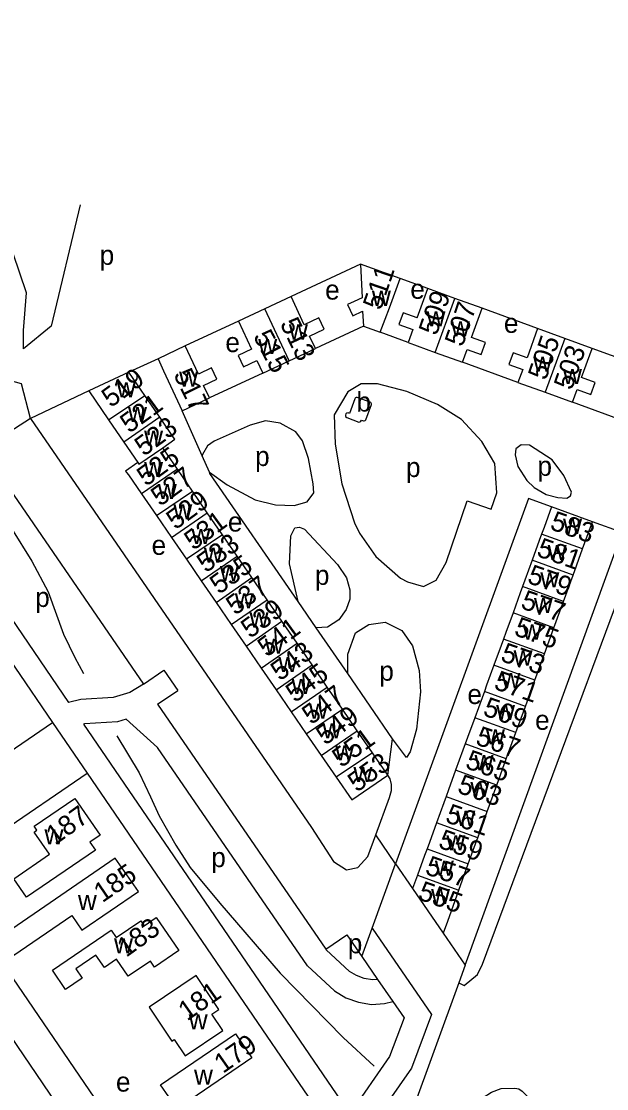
# Model space of a CAD drawing. Extents: x 154320 to 156262, y 382651 to 384180.
# Drawn here: x 155711.8 to 155831.3, y 383414.4 to 383632.2 of the extents above; entities that cross this region are included whole.
import ezdxf

# ---------------------------------------------------------------- set-up
doc = ezdxf.new("R2010")
doc.units = 0
for name, color, linetype in [('BLT_Basislijn', 7, 'Continuous'), ('BLT_Bebouwing', 7, 'Continuous'), ('BLT_Centroide', 7, 'Continuous'), ('BLT_Huisnummer', 7, 'Continuous'), ('BLT_Huisnummer_ tussenligend', 7, 'Continuous'), ('BLT_Onderverdeling_panden', 7, 'Continuous'), ('BLT_Vlakafsluiter', 7, 'Continuous')]:
    doc.layers.add(name, color=color, linetype=linetype)

msp = doc.modelspace()

# ---------------------------------------------------------------- linework, layer by layer
at = {"layer": 'BLT_Basislijn'}
for p, q in [((155723.77, 383594.72), (155717.9, 383569.98)), ((155781.07, 383582.65), (155766.86, 383576.05)), ((155794.76, 383577.69), (155789.13, 383579.71)), ((155817.21, 383569.54), (155805.91, 383573.63)), ((155717.9, 383569.98), (155712.22, 383565.38)), ((155756.13, 383571.03), (155745.24, 383565.96)), ((155781.64, 383569.99), (155771.84, 383565.42)), ((155790.76, 383566.65), (155785.09, 383568.73)), ((155839.44, 383561.42), (155828.37, 383565.46)), ((155739.71, 383563.35), (155733.71, 383560.61)), ((155813.2, 383558.51), (155801.9, 383562.62)), ((155761.08, 383560.4), (155750.18, 383555.34)), ((155835.65, 383550.35), (155824.35, 383554.45)), ((155748.71, 383543.49), (155744.6, 383552.72)), ((155750.19, 383540.18), (155748.71, 383543.49)), ((155778.43, 383499.07), (155772, 383508.41)), ((155736.76, 383496.93), (155740.88, 383499.77)), ((155740.88, 383499.77), (155743.72, 383495.64)), ((155787.59, 383485.76), (155778.43, 383499.07)), ((155739.6, 383492.81), (155743.72, 383495.64)), ((155739.6, 383492.81), (155773.99, 383442.8)), ((155689.88, 383469.84), (155718.17, 383489.1)), ((155695.34, 383458.35), (155725.22, 383478.78)), ((155788.18, 383460.25), (155791.67, 383455.18)), ((155695.34, 383458.35), (155746.12, 383384.05)), ((155736.8, 383385.3), (155689.56, 383454.4)), ((155781.31, 383441.34), (155784.53, 383436.66)), ((155802.41, 383439.57), (155801.1, 383435.95)), ((155784.53, 383436.66), (155787.63, 383432.15)), ((155801.1, 383435.95), (155788.64, 383401.73))]:
    msp.add_line(p, q, dxfattribs=at)
for points in [[(155712.22, 383565.38), (155712.25, 383569.11), (155712.86, 383576.76), (155710.15, 383584.83), (155703.72, 383589.45), (155702.06, 383598.56), (155698.39, 383604.03), (155691.52, 383607.97), (155684.3, 383610.54), (155677.08, 383613.11), (155657.33, 383632.2)], [(155713.63, 383551.16), (155711.84, 383558.19), (155704.16, 383560.3), (155698.52, 383562.36), (155692.32, 383562.27)], [(155725.56, 383556.77), (155713.63, 383551.16)], [(155699.18, 383552.32), (155699.56, 383547.02), (155700.26, 383542.84), (155701.35, 383540.44), (155704.4, 383535.59), (155709.75, 383528.69), (155713.91, 383522), (155717.27, 383515.75), (155720.43, 383507.15), (155722.7, 383502.36), (155724.5, 383499.1)], [(155713.63, 383551.16), (155703.82, 383544.84), (155736.76, 383496.93)], [(155713.63, 383551.16), (155771.03, 383467.65), (155775.5, 383460.75), (155778.15, 383458.99), (155780.51, 383459.46), (155782.53, 383461.72), (155784.15, 383466.14)], [(155750.19, 383540.18), (155753.83, 383537.57), (155759.51, 383534.55), (155763.68, 383533.5), (155767.47, 383533.36), (155770.12, 383534.12), (155771.53, 383535.96), (155771.41, 383537.8), (155770.4, 383542.99), (155769.19, 383546.57), (155767.83, 383548.45), (155764.67, 383550.18), (155761.67, 383550.66), (155758.53, 383549.75)], [(155758.53, 383549.75), (155751.17, 383546.54), (155749.78, 383545.57), (155748.77, 383543.82), (155748.71, 383543.49)], [(155768.3, 383513.79), (155750.3, 383539.93), (155750.19, 383540.18)], [(155815.36, 383534.83), (155788.18, 383460.25)], [(155820.06, 383533.12), (155815.36, 383534.83)], [(155651.71, 383522.17), (155669.01, 383530.29), (155671.62, 383531.32), (155674.82, 383532.09), (155679.01, 383532.3), (155683.15, 383531.66), (155687.05, 383530.13), (155690.62, 383527.92), (155693.07, 383525.51), (155695.02, 383522.96), (155718.17, 383489.1)], [(155768.3, 383513.79), (155766.56, 383521.48), (155766.84, 383527.19), (155767.66, 383528.8), (155768.61, 383528.97), (155769.58, 383528.54), (155776.35, 383521.32), (155778.18, 383518.65), (155778.89, 383516.2), (155778.87, 383514.26), (155778.11, 383512.13), (155776.63, 383510.07), (155774.32, 383508.58), (155772, 383508.41)], [(155834.5, 383527.86), (155828.41, 383530.07)], [(155802.41, 383439.57), (155834.5, 383527.86)], [(155699.07, 383525.89), (155721.42, 383493.2)], [(155801.1, 383435.95), (155802.24, 383435.39), (155804.95, 383437.68), (155805.97, 383439.73), (155834.64, 383517.07), (155835.62, 383518.64), (155836.89, 383519.06), (155839.22, 383519.08), (155863.38, 383510.83), (155865.12, 383510.28), (155870.15, 383508.84), (155869.25, 383505.27), (155870.15, 383504.05), (155871.64, 383502.96)], [(155772, 383508.41), (155768.3, 383513.79)], [(155778.43, 383499.07), (155778.43, 383503.05), (155780.02, 383507.41), (155782.72, 383509.07), (155786.1, 383509.56), (155789.48, 383507.89), (155789.48, 383507.89), (155791.67, 383504.76), (155793.03, 383499.67), (155793.28, 383495.37), (155792.48, 383487.74), (155791.19, 383483.13), (155790.42, 383481.94), (155787.59, 383485.76)], [(155736.76, 383496.93), (155733.93, 383495.18), (155730.57, 383494.2), (155723.96, 383493.77), (155721.42, 383493.2)], [(155718.17, 383489.1), (155725.22, 383478.78)], [(155733.18, 383489.76), (155731.44, 383489.25), (155724.67, 383488.8), (155724.46, 383488.76)], [(155770.25, 383439.41), (155739.62, 383483.96), (155733.18, 383489.76)], [(155724.46, 383488.76), (155778.83, 383409.21)], [(155731.27, 383486.4), (155735.86, 383478.8), (155738.14, 383473.92), (155739.95, 383470.03), (155743.32, 383464.03), (155746.24, 383459.5), (155752.33, 383452.24), (155764.66, 383437.95), (155777.51, 383424.78), (155783.83, 383418.94)], [(155786.63, 383478.34), (155787.59, 383485.76)], [(155725.22, 383478.78), (155776.01, 383404.48)], [(155784.15, 383466.14), (155786.93, 383473.75), (155787.37, 383475.22), (155787.37, 383476.43), (155787.09, 383477.6), (155786.63, 383478.34)], [(155783.41, 383447.12), (155788.18, 383460.25)], [(155773.99, 383442.8), (155778.25, 383445.76), (155781.31, 383441.34)], [(155781.31, 383441.34), (155783.41, 383447.12)], [(155783.41, 383447.12), (155795.54, 383429.47), (155791.45, 383418.56), (155781.85, 383404.79)], [(155797.95, 383446.06), (155802.41, 383439.57)], [(155784.53, 383436.66), (155783.49, 383436.59), (155781.82, 383436.86), (155780.2, 383437.42), (155778.81, 383438.28), (155774.06, 383442.7), (155773.99, 383442.8)], [(155770.25, 383439.41), (155775.76, 383434.29), (155778.05, 383432.87), (155780.6, 383432), (155783.26, 383431.56), (155785.95, 383431.75), (155787.63, 383432.15)], [(155787.63, 383432.15), (155789.95, 383428.78), (155786.99, 383420.9), (155778.83, 383409.21)]]:
    msp.add_lwpolyline(points, dxfattribs=at)
for points in [[(155784.52, 383558.23), (155781.17, 383558.23), (155778.45, 383556.56), (155775.64, 383551.88), (155775.88, 383545.9), (155777.21, 383537.81), (155779.85, 383529.83), (155780.81, 383527.76), (155784.17, 383522.98), (155789.18, 383518.56), (155790.64, 383517.77), (155793.88, 383516.88), (155796.51, 383518.11), (155798.54, 383521.73), (155802.8, 383534.35), (155807.69, 383532.62), (155808.86, 383535.94), (155808.49, 383541.93), (155805.84, 383546.45), (155801.65, 383550.96), (155796.77, 383553.98), (155790.52, 383556.64)], [(155823.18, 383534.9), (155823.92, 383535.32), (155824.1, 383536.13), (155822.59, 383539.53), (155820.21, 383542.67), (155815.58, 383545.72), (155813.83, 383545.77), (155812.78, 383544.93), (155812.61, 383543.72), (155813.2, 383541.35), (155815.02, 383538.47), (155816.49, 383537.05), (155818.92, 383535.6), (155821.3, 383535.03)], [(155804.58, 383408.39), (155804.7, 383409.7), (155805.12, 383411.15), (155806.09, 383412.58), (155807.78, 383413.64), (155809.74, 383414.38), (155812.53, 383414.47), (155813.38, 383414.34), (155814.07, 383413.82), (155816.13, 383411.78), (155817.37, 383409.78), (155818.05, 383407.74), (155818.02, 383406.53), (155816.72, 383403.75), (155815.78, 383403), (155814.4, 383402.09), (155813.12, 383401.41), (155811.21, 383400.86), (155810.01, 383400.98), (155809.47, 383401.2), (155806.52, 383403.11), (155805.89, 383403.67), (155805.69, 383403.98), (155804.92, 383406.4)]]:
    msp.add_lwpolyline(points, close=True, dxfattribs=at)
at = {"layer": 'BLT_Bebouwing'}
for p, q in [((155781.07, 383582.65), (155781.36, 383575.79)), ((155789.13, 383579.71), (155781.07, 383582.65)), ((155786.94, 383573.75), (155789.13, 383579.71)), ((155792.6, 383571.71), (155794.76, 383577.69)), ((155800.33, 383575.66), (155794.76, 383577.69)), ((155766.86, 383576.05), (155761.49, 383573.54)), ((155769.56, 383570.29), (155766.86, 383576.05)), ((155779.72, 383575.02), (155778.42, 383574.41)), ((155778.42, 383574.41), (155779.49, 383572.09)), ((155781.36, 383575.79), (155779.72, 383575.02)), ((155805.91, 383573.63), (155800.33, 383575.66)), ((155761.49, 383573.54), (155756.13, 383571.03)), ((155779.49, 383572.09), (155781.48, 383573.02)), ((155781.48, 383573.02), (155781.64, 383569.99)), ((155786.06, 383571.38), (155786.94, 383573.75)), ((155789.77, 383572.73), (155788.9, 383570.33)), ((155792.6, 383571.71), (155789.77, 383572.73)), ((155803.73, 383567.65), (155805.91, 383573.63)), ((155756.13, 383571.03), (155758.8, 383565.27)), ((155772.51, 383571.67), (155769.56, 383570.29)), ((155773.59, 383569.34), (155772.51, 383571.67)), ((155781.64, 383569.99), (155785.09, 383568.73)), ((155785.09, 383568.73), (155786.06, 383571.38)), ((155788.9, 383570.33), (155791.71, 383569.29)), ((155770.65, 383567.96), (155773.59, 383569.34)), ((155771.84, 383565.42), (155770.65, 383567.96)), ((155791.71, 383569.29), (155790.76, 383566.65)), ((155806.56, 383566.63), (155803.73, 383567.65)), ((155817.21, 383569.54), (155815.04, 383563.54)), ((155822.79, 383567.5), (155817.21, 383569.54)), ((155828.37, 383565.46), (155822.79, 383567.5)), ((155745.24, 383565.96), (155739.71, 383563.35)), ((155747.94, 383560.21), (155745.24, 383565.96)), ((155758.8, 383565.27), (155756.08, 383564)), ((155766.46, 383562.91), (155771.84, 383565.42)), ((155790.76, 383566.65), (155796.32, 383564.64)), ((155805.68, 383564.21), (155806.56, 383566.63)), ((155826.2, 383559.49), (155828.37, 383565.46)), ((155739.71, 383563.35), (155740.82, 383560.9)), ((155756.08, 383564), (155757.16, 383561.69)), ((155796.32, 383564.64), (155801.9, 383562.62)), ((155801.9, 383562.62), (155802.85, 383565.24)), ((155802.85, 383565.24), (155805.68, 383564.21)), ((155812.21, 383564.57), (155811.34, 383562.17)), ((155815.04, 383563.54), (155812.21, 383564.57)), ((155740.82, 383560.9), (155744.6, 383552.72)), ((155750.65, 383561.47), (155747.94, 383560.21)), ((155751.73, 383559.15), (155750.65, 383561.47)), ((155757.16, 383561.69), (155759.88, 383562.96)), ((155759.88, 383562.96), (155761.08, 383560.4)), ((155761.08, 383560.4), (155766.46, 383562.91)), ((155811.34, 383562.17), (155814.16, 383561.15)), ((155814.16, 383561.15), (155813.2, 383558.51)), ((155733.71, 383560.61), (155725.56, 383556.77)), ((155736.24, 383556.93), (155733.71, 383560.61)), ((155749, 383557.88), (155751.73, 383559.15)), ((155828.98, 383558.47), (155826.2, 383559.49)), ((155725.56, 383556.77), (155729.62, 383550.85)), ((155737, 383555.83), (155736.24, 383556.93)), ((155750.18, 383555.34), (155749, 383557.88)), ((155813.2, 383558.51), (155818.76, 383556.48)), ((155824.35, 383554.45), (155825.28, 383557.08)), ((155825.28, 383557.08), (155828.1, 383556.06)), ((155828.1, 383556.06), (155828.98, 383558.47)), ((155739.59, 383552.06), (155737, 383555.83)), ((155744.6, 383552.72), (155750.18, 383555.34)), ((155818.76, 383556.48), (155824.35, 383554.45)), ((155729.62, 383550.85), (155732.7, 383546.34)), ((155740.06, 383551.38), (155739.59, 383552.06)), ((155742.88, 383547.28), (155740.06, 383551.38)), ((155732.7, 383546.34), (155735.57, 383542.16)), ((155743.14, 383546.91), (155742.88, 383547.28)), ((155743.66, 383540.78), (155740.68, 383545.12)), ((155735.57, 383542.16), (155733.08, 383540.41)), ((155733.08, 383540.41), (155733.27, 383540.15)), ((155733.27, 383540.15), (155733.65, 383539.65)), ((155733.65, 383539.65), (155736.33, 383535.74)), ((155746.71, 383536.33), (155743.66, 383540.78)), ((155736.33, 383535.74), (155739.37, 383531.32)), ((155749.76, 383531.9), (155746.71, 383536.33)), ((155820.06, 383533.12), (155818.51, 383528.86)), ((155828.41, 383530.07), (155820.06, 383533.12)), ((155739.37, 383531.32), (155742.44, 383526.86)), ((155752.84, 383527.42), (155749.76, 383531.9)), ((155818.51, 383528.86), (155818.03, 383527.56)), ((155826.39, 383524.51), (155828.41, 383530.07)), ((155742.44, 383526.86), (155745.5, 383522.4)), ((155755.86, 383523.03), (155752.84, 383527.42)), ((155817.55, 383526.25), (155816.08, 383522.2)), ((155818.03, 383527.56), (155817.55, 383526.25)), ((155824.44, 383519.16), (155826.39, 383524.51)), ((155745.5, 383522.4), (155748.54, 383517.99)), ((155758.84, 383518.71), (155755.86, 383523.03)), ((155816.08, 383522.2), (155814.61, 383518.15)), ((155748.54, 383517.99), (155751.57, 383513.58)), ((155761.97, 383514.16), (155758.84, 383518.71)), ((155814.61, 383518.15), (155814.13, 383516.85)), ((155822.49, 383513.8), (155824.44, 383519.16)), ((155813.65, 383515.54), (155812.18, 383511.48)), ((155814.13, 383516.85), (155813.65, 383515.54)), ((155751.57, 383513.58), (155754.63, 383509.12)), ((155765.01, 383509.75), (155761.97, 383514.16)), ((155820.55, 383508.44), (155822.49, 383513.8)), ((155812.18, 383511.48), (155810.7, 383507.44)), ((155754.63, 383509.12), (155757.69, 383504.67)), ((155768.1, 383505.26), (155765.01, 383509.75)), ((155810.7, 383507.44), (155810.23, 383506.13)), ((155818.6, 383503.09), (155820.55, 383508.44)), ((155757.69, 383504.67), (155760.76, 383500.21)), ((155771.14, 383500.84), (155768.1, 383505.26)), ((155809.75, 383504.83), (155808.27, 383500.77)), ((155810.23, 383506.13), (155809.75, 383504.83)), ((155816.65, 383497.73), (155818.6, 383503.09)), ((155760.76, 383500.21), (155763.82, 383495.76)), ((155774.24, 383496.33), (155771.14, 383500.84)), ((155808.27, 383500.77), (155806.8, 383496.73)), ((155814.7, 383492.37), (155816.65, 383497.73)), ((155763.82, 383495.76), (155766.89, 383491.28)), ((155777.35, 383491.82), (155774.24, 383496.33)), ((155806.8, 383496.73), (155806.33, 383495.42)), ((155805.85, 383494.12), (155804.37, 383490.07)), ((155806.33, 383495.42), (155805.85, 383494.12)), ((155766.89, 383491.28), (155769.97, 383486.8)), ((155780.39, 383487.41), (155777.35, 383491.82)), ((155812.76, 383487.02), (155814.7, 383492.37)), ((155804.37, 383490.07), (155802.9, 383486.03)), ((155783.47, 383482.93), (155780.39, 383487.41)), ((155810.81, 383481.67), (155812.76, 383487.02)), ((155769.97, 383486.8), (155773.03, 383482.35)), ((155802.43, 383484.72), (155801.95, 383483.41)), ((155802.9, 383486.03), (155802.43, 383484.72)), ((155786.63, 383478.34), (155783.47, 383482.93)), ((155801.95, 383483.41), (155800.47, 383479.35)), ((155773.03, 383482.35), (155776.09, 383477.9)), ((155808.87, 383476.3), (155810.81, 383481.67)), ((155779.25, 383473.3), (155786.63, 383478.34)), ((155800.47, 383479.35), (155799, 383475.32)), ((155776.09, 383477.9), (155779.25, 383473.3)), ((155806.92, 383470.94), (155808.87, 383476.3)), ((155798.52, 383474), (155798.04, 383472.68)), ((155799, 383475.32), (155798.52, 383474)), ((155798.04, 383472.68), (155796.57, 383468.64)), ((155804.97, 383465.58), (155806.92, 383470.94)), ((155796.57, 383468.64), (155795.1, 383464.59)), ((155803.04, 383460.22), (155804.79, 383465.1)), ((155804.79, 383465.1), (155804.97, 383465.58)), ((155794.62, 383463.28), (155794.14, 383461.97)), ((155795.1, 383464.59), (155794.62, 383463.28)), ((155794.14, 383461.97), (155792.67, 383457.93)), ((155801.11, 383454.86), (155803.04, 383460.22)), ((155792.67, 383457.93), (155791.67, 383455.18)), ((155791.67, 383455.18), (155797.95, 383446.06)), ((155798.84, 383448.56), (155801.11, 383454.86))]:
    msp.add_line(p, q, dxfattribs=at)
for points in [[(155780.35, 383555.41), (155780.19, 383555.43), (155780.04, 383555.37), (155779.93, 383555.26), (155779.86, 383555.13), (155778.82, 383552.18), (155778.52, 383552.29), (155778.26, 383552.25), (155778.08, 383552.07), (155777.98, 383551.79), (155778.01, 383551.53), (155778.24, 383551.33), (155780.72, 383550.41), (155780.93, 383550.45), (155781.12, 383550.6), (155781.22, 383550.81), (155781.64, 383550.66), (155781.81, 383550.65), (155781.97, 383550.7), (155782.08, 383550.79), (155782.14, 383550.89)], [(155782.14, 383550.89), (155783.26, 383553.98), (155783.26, 383554.15), (155783.21, 383554.28), (155783.13, 383554.38), (155783.01, 383554.46), (155780.35, 383555.41)], [(155740.68, 383545.12), (155740.65, 383545.16), (155743.14, 383546.91)], [(155798.84, 383448.56), (155798.8, 383448.45), (155797.95, 383446.06)]]:
    msp.add_lwpolyline(points, dxfattribs=at)
for points in [[(155722.74, 383473.61), (155727.9, 383466.08), (155725.81, 383464.65), (155726.93, 383463.03), (155712.87, 383453.41), (155710.28, 383457.21), (155717.54, 383462.18), (155714.43, 383466.72), (155714.97, 383467.09), (155714.41, 383467.91)], [(155730.98, 383461.43), (155707.64, 383445.38), (155710.25, 383441.58), (155722.07, 383449.69), (155724.14, 383446.67), (155735.68, 383454.59)], [(155718.18, 383438.51), (155730.16, 383446.7), (155731.18, 383445.23), (155736.18, 383448.64), (155736.9, 383447.62), (155739.34, 383449.28), (155743.94, 383442.56), (155738.98, 383439.16), (155738.14, 383440.39), (155733.61, 383437.28), (155731.24, 383440.75), (155728.78, 383439.07), (155727.02, 383441.61), (155722.94, 383438.78), (155724.21, 383436.91), (155720.83, 383434.62)], [(155747.49, 383437.43), (155737.87, 383430.97), (155742.51, 383424.07), (155742.99, 383424.4), (155745.26, 383421.05), (155752.93, 383426.25), (155750.68, 383429.56), (155752.14, 383430.54)], [(155740.22, 383415.12), (155755.49, 383425.56), (155758.85, 383420.64), (155743.58, 383410.2)]]:
    msp.add_lwpolyline(points, close=True, dxfattribs=at)
at = {"layer": 'BLT_Onderverdeling_panden'}
for p, q in [((155796.32, 383564.64), (155800.33, 383575.66)), ((155766.46, 383562.91), (155761.49, 383573.54)), ((155822.79, 383567.5), (155818.76, 383556.48)), ((155729.62, 383550.85), (155737, 383555.83)), ((155740.06, 383551.38), (155732.7, 383546.34)), ((155743.66, 383540.78), (155736.33, 383535.74)), ((155739.37, 383531.32), (155746.71, 383536.33)), ((155742.44, 383526.86), (155749.76, 383531.9)), ((155752.84, 383527.42), (155745.5, 383522.4)), ((155826.39, 383524.51), (155818.03, 383527.56)), ((155748.54, 383517.99), (155755.86, 383523.03)), ((155824.44, 383519.16), (155816.08, 383522.2)), ((155751.57, 383513.58), (155758.84, 383518.71)), ((155822.49, 383513.8), (155814.13, 383516.85)), ((155754.63, 383509.12), (155761.97, 383514.16)), ((155820.55, 383508.44), (155812.18, 383511.48)), ((155757.69, 383504.67), (155765.01, 383509.75)), ((155760.76, 383500.21), (155768.1, 383505.26)), ((155818.6, 383503.09), (155810.23, 383506.13)), ((155763.82, 383495.76), (155771.14, 383500.84)), ((155816.65, 383497.73), (155808.27, 383500.77)), ((155766.89, 383491.28), (155774.24, 383496.33)), ((155814.7, 383492.37), (155806.33, 383495.42)), ((155769.97, 383486.8), (155777.35, 383491.82)), ((155812.76, 383487.02), (155804.37, 383490.07)), ((155773.03, 383482.35), (155780.39, 383487.41)), ((155810.81, 383481.67), (155802.43, 383484.72)), ((155783.47, 383482.93), (155776.09, 383477.9)), ((155808.87, 383476.3), (155800.47, 383479.35)), ((155798.52, 383474), (155806.92, 383470.94)), ((155804.97, 383465.58), (155796.57, 383468.64)), ((155794.62, 383463.28), (155803.04, 383460.22)), ((155792.67, 383457.93), (155801.11, 383454.86))]:
    msp.add_line(p, q, dxfattribs=at)
msp.add_lwpolyline([(155735.57, 383542.16), (155735.79, 383541.83), (155740.68, 383545.12)], dxfattribs=at)
at = {"layer": 'BLT_Vlakafsluiter'}
msp.add_line((155788.18, 383460.25), (155784.15, 383466.14), dxfattribs=at)

# ---------------------------------------------------------------- texts
at = {"layer": 'BLT_Centroide'}
for s, p in [('p', (155727.78, 383582.5)), ('e', (155773.82, 383575.41)), ('e', (155791.21, 383575.57)), ('w', (155783.37, 383574.13)), ('w', (155794.52, 383569.95)), ('w', (155766.43, 383567.26)), ('w', (155799.52, 383567.92)), ('e', (155810.32, 383568.62)), ('e', (155753.45, 383564.69)), ('w', (155760.16, 383564.28)), ('w', (155816.3, 383560.68)), ('w', (155822.38, 383558.15)), ('w', (155744, 383557.64)), ('w', (155731.29, 383555.47)), ('b', (155780.21, 383552.55)), ('w', (155733.57, 383550.4)), ('w', (155736.86, 383545.58)), ('p', (155759.52, 383541.44)), ('w', (155736.86, 383539.19)), ('p', (155790.33, 383539.19)), ('p', (155817.17, 383539.44)), ('w', (155739.67, 383534.69)), ('w', (155742.83, 383530.57)), ('e', (155753.97, 383528.06)), ('w', (155822.4, 383527.59)), ('w', (155746.53, 383525.51)), ('e', (155738.39, 383523.31)), ('w', (155749.06, 383521.71)), ('w', (155819.26, 383522.26)), ('w', (155752.32, 383517.98)), ('p', (155771.73, 383517.18)), ('w', (155817.76, 383516.65)), ('p', (155714.62, 383512.67)), ('w', (155755.38, 383512.38)), ('w', (155816.44, 383511.46)), ('w', (155758.38, 383508.47)), ('w', (155814.17, 383506.02)), ('w', (155761.49, 383503.14)), ('w', (155764.28, 383499.37)), ('w', (155812.3, 383500.72)), ('p', (155784.88, 383497.62)), ('w', (155766.99, 383494.88)), ('w', (155809.82, 383496.09)), ('e', (155802.87, 383492.86)), ('w', (155770.54, 383489.84)), ('w', (155808.73, 383489.62)), ('e', (155816.69, 383487.6)), ('w', (155773.28, 383485.85)), ('w', (155806.66, 383484.62)), ('w', (155775.87, 383481.35)), ('w', (155804.33, 383479.35)), ('w', (155779.61, 383476.91)), ('w', (155803.48, 383473.85)), ('w', (155800.61, 383467.99)), ('w', (155716.52, 383464.19)), ('w', (155798.57, 383463)), ('p', (155750.57, 383459.57)), ('w', (155796.23, 383457.8)), ('w', (155795.45, 383452.05)), ('w', (155723.34, 383450.82)), ('w', (155730.72, 383441.97)), ('p', (155778.44, 383441.98)), ('w', (155745.97, 383426.43)), ('w', (155747.05, 383415.18)), ('e', (155731.11, 383413.75))]:
    msp.add_text(s, height=4, dxfattribs=at).set_placement(p)
at = {"layer": 'BLT_Huisnummer'}
for s, rotation, p in [('511', 71.0029, (155785.18, 383573.07)), ('509', 71.0029, (155796.56, 383567.89)), ('507', 71.0029, (155801.88, 383565.6)), ('513', 295.839, (155764.52, 383570.54)), ('515', 297.5185, (155759.05, 383567.95)), ('505', 71.0029, (155818.88, 383558.76)), ('503', 71.0029, (155824.16, 383556.76)), ('519', 36.1028, (155730.05, 383553.23)), ('517', 296.0789, (155742.78, 383560.13)), ('523', 36.1028, (155736.8, 383543.3)), ('527', 36.1028, (155740.12, 383533.07)), ('531', 36.1028, (155746.92, 383524.1)), ('583', 340.7306, (155819.52, 383528.59)), ('535', 36.1028, (155752.16, 383515.11)), ('579', 340.7306, (155814.88, 383517.66)), ('539', 36.1028, (155758.5, 383506.12)), ('575', 340.7306, (155812.2, 383506.98)), ('543', 36.1028, (155764.57, 383497.43)), ('571', 340.7306, (155808.07, 383496.02)), ('547', 36.1028, (155770.97, 383488.5)), ('551', 36.1028, (155777.13, 383479.74)), ('567', 340.7306, (155804.32, 383484.68)), ('553', 36.1028, (155780.31, 383474.72)), ('563', 340.7306, (155800.6, 383474.85)), ('187', 35.7267, (155718.66, 383463.94)), ('559', 340.7306, (155796.72, 383463.62)), ('185', 34.3546, (155728.33, 383452.2)), ('555', 340.7306, (155792.57, 383453.06)), ('183', 35.8967, (155733.21, 383441.05)), ('181', 35.0638, (155745.63, 383428.05)), ('179', 35.0638, (155752.96, 383417.34))]:
    msp.add_text(s, height=4, rotation=rotation, dxfattribs=at).set_placement(p)
at = {"layer": 'BLT_Huisnummer_ tussenligend'}
for s, rotation, p in [('521', 36.1028, (155733.83, 383548)), ('525', 36.1028, (155737.26, 383537.16)), ('529', 36.1028, (155743.26, 383528.3)), ('533', 36.1028, (155749.49, 383519.51)), ('581', 340.7306, (155816.81, 383523.12)), ('537', 36.1028, (155755.46, 383510.84)), ('577', 340.7306, (155813.55, 383512.47)), ('541', 36.1028, (155761.9, 383502.3)), ('573', 340.7306, (155809.43, 383501.72)), ('545', 36.1028, (155767.65, 383493.01)), ('569', 340.7306, (155805.84, 383490.62)), ('549', 36.1028, (155773.85, 383484.32)), ('565', 340.7306, (155802.23, 383479.84)), ('561', 340.7306, (155798.15, 383468.84)), ('557', 340.7306, (155794.02, 383458.23))]:
    msp.add_text(s, height=4, rotation=rotation, dxfattribs=at).set_placement(p)

doc.saveas('drawing.dxf')
